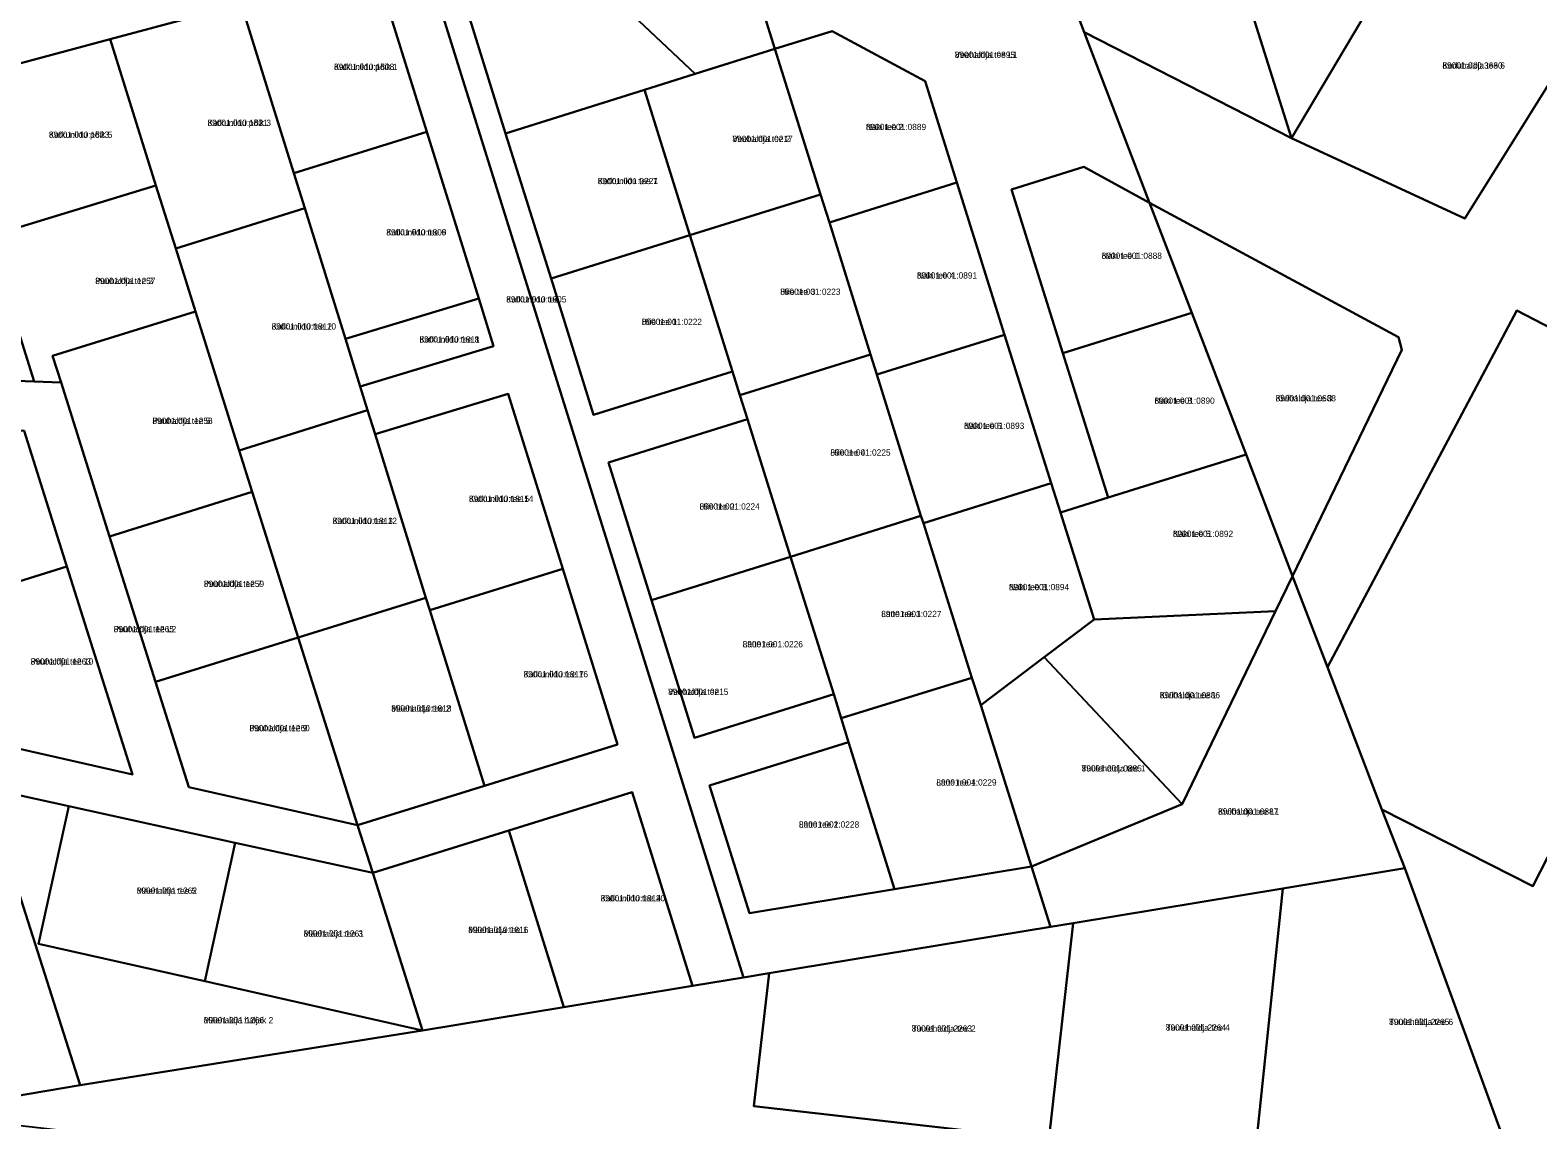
# Model space of a CAD drawing. Extents: x 526849 to 562296, y 6591741 to 6618546.
# Drawn here: x 551687.9 to 552050.8, y 6594708.4 to 6594970.6 of the extents above; entities that cross this region are included whole.
import ezdxf

# ---------------------------------------------------------------- set-up
doc = ezdxf.new("R2010")
doc.units = 0
for name, color, linetype in [('L_AADRESS', 7, 'Continuous'), ('PIIR', 7, 'Continuous'), ('TUNNUS', 7, 'Continuous')]:
    doc.layers.add(name, color=color, linetype=linetype)

msp = doc.modelspace()

# ---------------------------------------------------------------- linework, layer by layer
at = {"layer": 'PIIR'}
for points in [[(551759.77, 6595061.95), (551859.59, 6594742.68), (551847.32, 6594740.71), (551832.82, 6594787.3), (551803.13, 6594778.06), (551770.36, 6594767.89), (551766.67, 6594779.35), (551797.25, 6594788.8), (551829.25, 6594798.76), (551816.11, 6594841.01), (551803, 6594883.14), (551770.92, 6594873.43), (551769.13, 6594879.16), (551767.35, 6594884.88), (551799.43, 6594894.6), (551795.87, 6594906.06), (551783.37, 6594946.2), (551771.13, 6594985.56)], [(551788.52, 6594990.18), (551802.34, 6594945.79), (551813.3, 6594910.88), (551823.53, 6594878.11), (551856.97, 6594888.53), (551858.72, 6594882.81), (551860.54, 6594877.04), (551827.1, 6594866.63), (551837.49, 6594833.51), (551847.84, 6594800.36), (551881.36, 6594810.82), (551883.14, 6594805.04), (551884.93, 6594799.33), (551851.42, 6594788.9), (551861.03, 6594758.17), (551895.93, 6594763.92), (551928.94, 6594769.37), (551933.51, 6594754.87), (551865.8, 6594743.73), (551859.59, 6594742.68), (551759.77, 6595061.95)], [(552104.85, 6594872.56), (552045.81, 6594903.16), (552000.23, 6594817.35), (551991.79, 6594839.27), (552018.07, 6594893.69), (552017.28, 6594896.75), (551957.39, 6594929.12), (551941.66, 6594970.16), (551991.51, 6594944.66), (552033.26, 6594925.31), (552064.21, 6594974.91), (552023.02, 6594997.61), (552003.81, 6595008.42), (551974.3, 6594999.43), (551935.06, 6594987.46), (551930.78, 6594998.59), (551947.35, 6595003.79), (551986.54, 6595015.77), (552044.91, 6595033.51), (552097.75, 6595001.16)], [(551863.58, 6594977.67), (551867.13, 6594966.14), (551847.97, 6594960.13), (551810.06, 6594995.92)], [(551738.72, 6594976.9), (551707.17, 6594968.47), (551666.13, 6594957.51)], [(552057.12, 6594664.14), (552047.5, 6594690.41), (552018.78, 6594768.97), (552013.32, 6594783.13), (552049.67, 6594764.62), (552104.85, 6594872.56)]]:
    msp.add_lwpolyline(points, dxfattribs=at)
for points in [[(551991.51, 6594944.66), (551974.3, 6594999.43), (552003.81, 6595008.42), (552023.02, 6594997.61)], [(551867.13, 6594966.14), (551863.58, 6594977.67), (551908.25, 6594991.6), (551930.78, 6594998.59), (551935.06, 6594987.46), (551941.66, 6594970.16), (551957.39, 6594929.12), (551941.53, 6594937.72), (551924.1, 6594932.29), (551936.49, 6594892.92), (551947.43, 6594858.18), (551935.91, 6594854.56), (551933.71, 6594861.62), (551922.43, 6594897.34), (551911.01, 6594933.96), (551903.33, 6594958.39), (551880.99, 6594970.43)], [(551941.66, 6594970.16), (551935.06, 6594987.46), (551974.3, 6594999.43), (551991.51, 6594944.66)], [(551802.34, 6594945.79), (551788.52, 6594990.18), (551810.06, 6594995.92), (551847.97, 6594960.13), (551835.77, 6594956.3)], [(552064.21, 6594974.91), (552033.26, 6594925.31), (551991.51, 6594944.66), (552023.02, 6594997.61)], [(551738.72, 6594976.9), (551771.13, 6594985.56), (551783.37, 6594946.2), (551751.37, 6594936.25)], [(551707.17, 6594968.47), (551738.72, 6594976.9), (551751.37, 6594936.25), (551754, 6594927.78), (551722.93, 6594918.07), (551718.14, 6594933.23)], [(551878.13, 6594931.06), (551867.13, 6594966.14), (551880.99, 6594970.43), (551903.33, 6594958.39), (551911.01, 6594933.96), (551880.28, 6594924.36)], [(551666.13, 6594957.51), (551707.17, 6594968.47), (551718.14, 6594933.23), (551677.87, 6594920.99)], [(551846.72, 6594921.32), (551835.77, 6594956.3), (551847.97, 6594960.13), (551867.13, 6594966.14), (551878.13, 6594931.06)], [(551813.3, 6594910.88), (551802.34, 6594945.79), (551835.77, 6594956.3), (551846.72, 6594921.32)], [(551751.37, 6594936.25), (551783.37, 6594946.2), (551795.87, 6594906.06), (551763.79, 6594896.34), (551754, 6594927.78)], [(551936.49, 6594892.92), (551924.1, 6594932.29), (551941.53, 6594937.72), (551957.39, 6594929.12), (551967.57, 6594902.64)], [(551688.89, 6594886.09), (551677.87, 6594920.99), (551718.14, 6594933.23), (551722.93, 6594918.07), (551727.69, 6594902.96), (551693.29, 6594892.25), (551695.32, 6594885.84)], [(551890.18, 6594892.6), (551880.28, 6594924.36), (551911.01, 6594933.96), (551922.43, 6594897.34), (551891.7, 6594887.77)], [(551856.97, 6594888.53), (551846.72, 6594921.32), (551878.13, 6594931.06), (551880.28, 6594924.36), (551890.18, 6594892.6), (551858.72, 6594882.81)], [(551722.93, 6594918.07), (551754, 6594927.78), (551763.79, 6594896.34), (551767.35, 6594884.88), (551769.13, 6594879.16), (551738.24, 6594869.47), (551727.69, 6594902.96)], [(551991.79, 6594839.27), (551980.62, 6594868.53), (551967.57, 6594902.64), (551957.39, 6594929.12), (552017.28, 6594896.75), (552018.07, 6594893.69)], [(551688.89, 6594886.09), (551645.64, 6594887.7), (551638.87, 6594909.09), (551677.87, 6594920.99)], [(551823.53, 6594878.11), (551813.3, 6594910.88), (551846.72, 6594921.32), (551856.97, 6594888.53)], [(551763.79, 6594896.34), (551795.87, 6594906.06), (551799.43, 6594894.6), (551767.35, 6594884.88)], [(551741.36, 6594859.51), (551707, 6594848.81), (551695.32, 6594885.84), (551693.29, 6594892.25), (551727.69, 6594902.96), (551738.24, 6594869.47)], [(551947.43, 6594858.18), (551936.49, 6594892.92), (551967.57, 6594902.64), (551980.62, 6594868.53)], [(552000.23, 6594817.35), (552045.81, 6594903.16), (552104.85, 6594872.56), (552049.67, 6594764.62), (552013.32, 6594783.13)], [(551902.33, 6594853.77), (551891.7, 6594887.77), (551922.43, 6594897.34), (551933.71, 6594861.62), (551902.96, 6594852.03)], [(551860.54, 6594877.04), (551858.72, 6594882.81), (551890.18, 6594892.6), (551891.7, 6594887.77), (551902.33, 6594853.77), (551870.94, 6594843.9)], [(551697.21, 6594783.9), (551677.05, 6594788.29), (551673.21, 6594800.42), (551712.54, 6594791.53), (551696.71, 6594841.59), (551686.41, 6594874.19), (551649.44, 6594875.59), (551645.64, 6594887.7), (551688.89, 6594886.09), (551695.32, 6594885.84), (551707, 6594848.81), (551718.08, 6594813.82), (551726.09, 6594788.48), (551766.67, 6594779.35), (551770.36, 6594767.89), (551737.21, 6594775.1)], [(551770.92, 6594873.43), (551803, 6594883.14), (551816.11, 6594841.01), (551784.1, 6594831.05), (551783.16, 6594834.07)], [(551738.24, 6594869.47), (551769.13, 6594879.16), (551770.92, 6594873.43), (551783.16, 6594834.07), (551752.39, 6594824.51), (551741.36, 6594859.51)], [(551696.71, 6594841.59), (551663.49, 6594831.21), (551657.36, 6594850.5), (551649.44, 6594875.59), (551686.41, 6594874.19)], [(551837.49, 6594833.51), (551827.1, 6594866.63), (551860.54, 6594877.04), (551870.94, 6594843.9)], [(551944.06, 6594828.85), (551935.91, 6594854.56), (551947.43, 6594858.18), (551980.62, 6594868.53), (551991.79, 6594839.27), (551987.65, 6594830.82)], [(551914.6, 6594814.82), (551902.96, 6594852.03), (551933.71, 6594861.62), (551935.91, 6594854.56), (551944.06, 6594828.85), (551931.99, 6594819.72), (551916.74, 6594808.2)], [(551752.39, 6594824.51), (551718.08, 6594813.82), (551707, 6594848.81), (551741.36, 6594859.51)], [(551881.36, 6594810.82), (551870.94, 6594843.9), (551902.33, 6594853.77), (551902.96, 6594852.03), (551914.6, 6594814.82), (551883.14, 6594805.04)], [(551847.84, 6594800.36), (551837.49, 6594833.51), (551870.94, 6594843.9), (551881.36, 6594810.82)], [(551712.54, 6594791.53), (551673.21, 6594800.42), (551663.49, 6594831.21), (551696.71, 6594841.59)], [(551784.1, 6594831.05), (551816.11, 6594841.01), (551829.25, 6594798.76), (551797.25, 6594788.8)], [(551933.51, 6594754.87), (551928.94, 6594769.37), (551965.25, 6594784.38), (551987.65, 6594830.82), (551991.79, 6594839.27), (552000.23, 6594817.35), (552013.32, 6594783.13), (552018.78, 6594768.97), (551989.46, 6594764.09), (551939, 6594755.73)], [(551752.39, 6594824.51), (551783.16, 6594834.07), (551784.1, 6594831.05), (551797.25, 6594788.8), (551766.67, 6594779.35)], [(551965.25, 6594784.38), (551931.99, 6594819.72), (551944.06, 6594828.85), (551987.65, 6594830.82)], [(551766.67, 6594779.35), (551726.09, 6594788.48), (551718.08, 6594813.82), (551752.39, 6594824.51)], [(551928.94, 6594769.37), (551916.74, 6594808.2), (551931.99, 6594819.72), (551965.25, 6594784.38)], [(551884.93, 6594799.33), (551883.14, 6594805.04), (551914.6, 6594814.82), (551916.74, 6594808.2), (551928.94, 6594769.37), (551895.93, 6594763.92)], [(551861.03, 6594758.17), (551851.42, 6594788.9), (551884.93, 6594799.33), (551895.93, 6594763.92)], [(551552.18, 6594719.67), (551538.84, 6594759.87), (551542.38, 6594759.49), (551572.97, 6594756.21), (551606.55, 6594752.64), (551640.12, 6594751.79), (551677.03, 6594750.82), (551677.05, 6594788.29), (551699.93, 6594716.74), (551659.72, 6594709.93), (551593.37, 6594713.2), (551554.8, 6594719.26)], [(551782.31, 6594729.91), (551699.93, 6594716.74), (551677.05, 6594788.29), (551697.21, 6594783.9), (551689.94, 6594750.77), (551729.91, 6594741.77)], [(551803.13, 6594778.06), (551832.82, 6594787.3), (551847.32, 6594740.71), (551816.33, 6594735.57)], [(551729.91, 6594741.77), (551689.94, 6594750.77), (551697.21, 6594783.9), (551737.21, 6594775.1)], [(551770.36, 6594767.89), (551803.13, 6594778.06), (551816.33, 6594735.57), (551782.31, 6594729.91)], [(551782.31, 6594729.91), (551729.91, 6594741.77), (551737.21, 6594775.1), (551770.36, 6594767.89)], [(551982.56, 6594697.9), (551989.46, 6594764.09), (552018.78, 6594768.97), (552047.5, 6594690.41)], [(551933.1, 6594703.58), (551939, 6594755.73), (551989.46, 6594764.09), (551982.56, 6594697.9)], [(551862.12, 6594711.75), (551865.8, 6594743.73), (551933.51, 6594754.87), (551939, 6594755.73), (551933.1, 6594703.58)], [(551782.31, 6594729.91), (551816.33, 6594735.57), (551847.32, 6594740.71), (551859.59, 6594742.68), (551865.8, 6594743.73), (551862.12, 6594711.75), (551933.1, 6594703.58), (551982.56, 6594697.9), (552047.5, 6594690.41), (552057.12, 6594664.14), (551659.72, 6594709.93), (551699.93, 6594716.74)]]:
    msp.add_lwpolyline(points, close=True, dxfattribs=at)

# ---------------------------------------------------------------- texts
at = {"layer": 'L_AADRESS'}
for s, p in [('Katkuniidu põik 1', (551761.04, 6594961.06)), ('Veehaldja tee L1', (551910.48, 6594963.96)), ('Koduhaldja tee 6', (552027.86, 6594961.38)), ('Katkuniidu põik 3', (551730.59, 6594947.59)), ('Näki tee 2', (551889.07, 6594946.59)), ('Katkuniidu põik 5', (551692.4, 6594944.73)), ('Veehaldja tee 2', (551856.95, 6594943.72)), ('Katkuniidu tee 7', (551824.53, 6594933.58)), ('Katkuniidu tee 6', (551773.62, 6594921.24)), ('Näki tee 1', (551945.84, 6594915.61)), ('Puuhaldja tee 3', (551703.55, 6594909.54)), ('Näki tee 4', (551901.36, 6594910.86)), ('Hiie tee 3', (551868.45, 6594906.95)), ('Katkuniidu tee', (551802.49, 6594905.11)), ('Hiie tee 1', (551835.13, 6594899.71)), ('Katkuniidu tee 10', (551746.03, 6594898.6)), ('Katkuniidu tee 8', (551781.61, 6594895.47)), ('Näki tee 3', (551958.55, 6594880.73)), ('Kivihaldja tee 3', (551987.73, 6594881.31)), ('Puuhaldja tee 5', (551717.32, 6594875.88)), ('Näki tee 6', (551912.71, 6594874.69)), ('Hiie tee 4', (551880.52, 6594868.25)), ('Katkuniidu tee 14', (551793.52, 6594857.12)), ('Hiie tee 2', (551849.02, 6594855.28)), ('Katkuniidu tee 12', (551760.7, 6594851.8)), ('Näki tee 5', (551962.98, 6594848.69)), ('Puuhaldja tee 7', (551729.7, 6594836.66)), ('Näki tee 8', (551923.51, 6594835.88)), ('Lätte tee 3', (551892.77, 6594829.4)), ('Puuhaldja tee L2', (551708, 6594825.77)), ('Lätte tee 1', (551859.42, 6594822.13)), ('Puuhaldja tee 10', (551688.02, 6594817.97)), ('Katkuniidu tee 16', (551806.68, 6594814.9)), ('Veehaldja tee', (551841.48, 6594810.67)), ('Kivihaldja tee 1', (551959.82, 6594809.86)), ('Mäehaldja tee 2', (551774.82, 6594806.67)), ('Puuhaldja tee 9', (551740.68, 6594801.93)), ('Tuulehaldja tee 1', (551941, 6594792.25)), ('Lätte tee 4', (551906.04, 6594788.87)), ('Kivihaldja tee L1', (551973.86, 6594781.87)), ('Lätte tee 2', (551872.96, 6594778.75)), ('Mäehaldja tee 5', (551713.56, 6594762.83)), ('Katkuniidu tee 20', (551825.23, 6594760.99)), ('Mäehaldja tee 3', (551753.73, 6594752.51)), ('Mäehaldja tee 1', (551793.34, 6594753.38)), ('Mäehaldja haljak 2', (551729.68, 6594731.66)), ('Tuulehaldja tee 2', (551900.12, 6594729.65)), ('Tuulehaldja tee 4', (551961.28, 6594729.88)), ('Tuulehaldja tee 6', (552015.03, 6594731.25))]:
    msp.add_text(s, height=1.5, dxfattribs=at).set_placement(p)
at = {"layer": 'TUNNUS'}
for s, p in [('89001:010:1808', (551761.04, 6594961.06)), ('89001:001:0895', (551910.48, 6594963.96)), ('89001:010:3630', (552027.86, 6594961.38)), ('89001:010:1821', (551730.59, 6594947.59)), ('89001:001:0889', (551889.07, 6594946.59)), ('89001:010:1823', (551692.4, 6594944.73)), ('89001:001:0217', (551856.95, 6594943.72)), ('89001:001:0221', (551824.53, 6594933.58)), ('89001:010:1809', (551773.62, 6594921.24)), ('89001:001:0888', (551945.84, 6594915.61)), ('89001:001:0891', (551901.36, 6594910.86)), ('89001:001:1257', (551703.55, 6594909.54)), ('89001:001:0223', (551868.45, 6594906.95)), ('89001:010:1805', (551802.49, 6594905.11)), ('89001:001:0222', (551835.13, 6594899.71)), ('89001:010:1812', (551746.03, 6594898.6)), ('89001:010:1811', (551781.61, 6594895.47)), ('89001:001:0890', (551958.55, 6594880.73)), ('89001:001:0688', (551987.73, 6594881.31)), ('89001:001:1258', (551717.32, 6594875.88)), ('89001:001:0893', (551912.71, 6594874.69)), ('89001:001:0225', (551880.52, 6594868.25)), ('89001:010:1815', (551793.52, 6594857.12)), ('89001:001:0224', (551849.02, 6594855.28)), ('89001:010:1813', (551760.7, 6594851.8)), ('89001:001:0892', (551962.98, 6594848.69)), ('89001:001:1259', (551729.7, 6594836.66)), ('89001:001:0894', (551923.51, 6594835.88)), ('89001:001:0227', (551892.77, 6594829.4)), ('89001:001:1265', (551708, 6594825.77)), ('89001:001:0226', (551859.42, 6594822.13)), ('89001:001:1263', (551688.02, 6594817.97)), ('89001:010:1817', (551806.68, 6594814.9)), ('89001:001:0215', (551841.48, 6594810.67)), ('89001:001:0886', (551959.82, 6594809.86)), ('89001:010:1818', (551774.82, 6594806.67)), ('89001:001:1260', (551740.68, 6594801.93)), ('89001:001:0885', (551941, 6594792.25)), ('89001:001:0229', (551906.04, 6594788.87)), ('89001:001:0887', (551973.86, 6594781.87)), ('89001:001:0228', (551872.96, 6594778.75)), ('89001:001:1262', (551713.56, 6594762.83)), ('89001:010:1814', (551825.23, 6594760.99)), ('89001:001:1261', (551753.73, 6594752.51)), ('89001:010:1816', (551793.34, 6594753.38)), ('89001:001:1266', (551729.68, 6594731.66)), ('89001:001:2263', (551900.12, 6594729.65)), ('89001:001:2264', (551961.28, 6594729.88)), ('89001:001:2265', (552015.03, 6594731.25))]:
    msp.add_text(s, height=1.5, dxfattribs=at).set_placement(p)

doc.saveas('drawing.dxf')
